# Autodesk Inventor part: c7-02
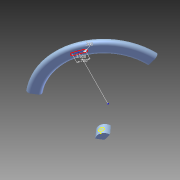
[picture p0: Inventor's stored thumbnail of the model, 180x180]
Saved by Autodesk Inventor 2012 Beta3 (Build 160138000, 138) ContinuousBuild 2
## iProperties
Created: 2010-12
Part Number: c7-02
Document SubType Name: Modeling
Designer: Thom Tremblay
Density: 1 g/cm^3
Material: Default
Author: Thom Tremblay
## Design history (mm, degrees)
sketch "Sketch2"
  geometry: L1 (0, 0)-(-11.43, 0); L2 (-11.43, 0)-(-11.43, 16.51); L3 (-11.43, 16.51)-(0, 16.51); L4 (0, 16.51)-(0, 0); L5 (-96.52, 66.04)-(-86.36, 66.04); L6 (-86.36, 76.2)-(-96.52, 76.2); L7 (-95.25, 74.93)-(-87.63, 74.93); L8 (-96.52, 76.2)-(-95.25, 74.93); L9 (-86.36, 76.2)-(-87.63, 74.93); A1 r 5.08 centre (-86.36, 71.12) between (-86.36, 66.04) and (-86.36, 76.2); A2 r 5.08 centre (-96.52, 71.12) between (-96.52, 76.2) and (-96.52, 66.04)
  constraints: 18 end point, 4 parallel, 4 point on circle, 4 tangent, 2 centre point, 2 horizontal, 2 perpendicular
  dimensions: "d6" = 16.51 distance of L1.end L2.end; "d7" = 22.86 diameter of L2 L4; "d10" = 5.08 radius of A1; "d11" = 20.32 dimension on A2 A1; "d12" = 3.81 distance from line of A1.centre L7; "d13" = 7.62 distance of L7.start L7.end; "d14" = 76.2 distance from line of L6.end L1; "d15" = 203.2 dimension on A2 L4
revolve "Revolution1" sketch "Sketch2" stored, may be unused: angle "d16" = 120 deg
sketch "Loft Sketch 1"
  geometry: L1 (-91.007, -8.89)-(-91.007, 8.89); A1 r 88.9 centre (0, 0) between (-88.479, 8.643) and (-88.479, -8.643); A2 r 93.98 centre (0, 0) between (-93.535, 9.137) and (-93.535, -9.137); A3 r 2.54 centre (-91.007, -8.89) between (-93.535, -9.137) and (-88.479, -8.643); A4 r 2.54 centre (-91.007, 8.89) between (-88.479, 8.643) and (-93.535, 9.137); 2 further points
  constraints: 8 point on circle, 4 centre point, 4 tangent, 2 end point, 1 coincident, 1 midpoint, 1 vertical
  dimensions: "d17" = 17.78 distance of L1.start L1.end; "d18" = 88.9 radius of A1; "d19" = 5.08 diameter of A4
sketch "Loft Sketch 2"
  geometry: C1 r 3.81 at (0, 7.62); 1 further point
  constraints: 1 centre point, 1 vertical alignment
  dimensions: "d63" = 7.62 diameter of C1; "d64" = 7.62 distance of point (0, 0) C1.centre
body "Solid1"
sketch "3D Sketch1"
node "Project from Loft Sketch 2"
